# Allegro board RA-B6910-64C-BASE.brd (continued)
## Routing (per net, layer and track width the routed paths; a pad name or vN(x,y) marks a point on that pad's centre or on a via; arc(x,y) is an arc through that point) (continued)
N17880169: length 4.9
  TOP w0.201: R153.2 52.63,90.73 v1(52.25,90.34) v3(52.25,89.08)
  BOTTOM w0.201: v3(52.25,89.08) v1(52.25,90.34)
N17880198: length 15.9
  TOP w0.201: U2.1 61.97,84.38 61.32,85.03 U2.19 56.75,85.03 56.12,85.65 R150.2 55.46,84.89 55.31,84.74 52.47,84.74 v1(52.16,85.05) 51.3,85.91 Q4.3
  BOTTOM w0.201: v3(51.56,85.6) 51.61,85.6 v1(52.16,85.05)
N17880220: length 4
  TOP w0.201: R156.1 65.77,90.22 v1(65.77,90.22) 65.13,89.58 U2.9
  BOTTOM w0.201: v1(65.77,90.22) 65.79,90.21 v3(65.79,89.28)
N17885472: length 3.7
  TOP w0.201: R125.1 126.1,150.8 125.47,150.17 v1(125.47,149.73) U1.91
  BOTTOM w0.201: v3(126.24,149.73) v1(125.47,149.73)
N17885725: length 5.6
  TOP w0.201: v1(116.33,135.25) 116.18,135.1 U1.132 113.75,135.1 112.94,134.29 R116.1
  BOTTOM w0.201: v3(116.33,136.27) v1(116.33,135.25)
N17885726: length 9.6
  TOP w0.201: v1(117.22,135.25) 116.56,134.6 U1.133 114.01,134.6 113.07,133.66 110.48,133.66 110.1,134.04 R121.1
  BOTTOM w0.201: v3(117.73,136.14) 117.73,135.76 v1(117.22,135.25)
N17894131: length 2.5
  TOP w0.201: R145.1 v1(139.79,150.85) 139.82,150.88 Q3.1
  BOTTOM w0.201: v3(139.79,149.99) v1(139.79,150.85)
N17894135: length 8.6
  TOP w0.201: Q3.3 137.53,152.01 136.73,151.21 R143.1 135.63,150.68 134.47,149.52 U1.73 134.47,147.98 v1(135.26,147.19)
  BOTTOM w0.201: v3(136.14,147.19) v1(135.26,147.19)
N17894645: length 4.1
  TOP w0.201: U1.78 131.97,149.31 v1(132.37,149.7) 132.58,149.91 R140.1
  BOTTOM w0.201: v1(132.37,149.7) 132.47,149.6 v3(132.47,148.55)
N17894809: length 3.6
  TOP w0.201: R128.1 128.39,150.55 127.97,150.13 v1(127.97,149.73) U1.86
  BOTTOM w0.201: v3(128.78,149.73) v1(127.97,149.73)
N17894927: length 5.2
  TOP w0.201: v1(124.21,155.07) 124.08,155.19 124.08,156.72 123.92,156.87 R117.1 122.65,156.87 122.29,156.52 Q1.1
  BOTTOM w0.201: v3(124.08,155.96) 124.08,155.19 v1(124.21,155.07)
N17894931: length 8
  TOP w0.201: U1.104 118.97,149.45 v1(119.24,149.72) R113.1 119.52,151.21 119.85,151.54 119.85,154.03 120.05,154.23 Q1.3
  BOTTOM w0.201: v1(119.24,149.72) 119.36,149.61 v3(120.14,149.61)
N17899016: length 3.9
  TOP w0.201: R137.1 138.31,141.28 v1(138.17,141.13) 137.64,140.6 U1.60
  BOTTOM w0.201: v1(138.17,141.13) 137.75,140.72 v3(137.29,140.72)
N17899017: length 5
  TOP w0.201: v1(135.13,140.33) 135.36,140.1 U1.59 138.26,140.1 138.42,140.26 R136.1
  BOTTOM w0.201: v1(135.13,140.33) 135.15,140.36 v3(135.15,141.35)
N17899018: length 5.7
  TOP w0.201: U1.54 137.58,137.6 138.62,136.55 140.96,136.55 R129.1
N17899019: length 3.9
  TOP w0.201: U1.61 137.22,141.1 v1(138.14,142.02) 138.15,142.02 138.43,142.29 R139.1
  BOTTOM w0.201: v1(138.14,142.02) 138.05,142.11 v3(137.29,142.11)
N17899020: length 7.5
  TOP w0.201: R132.1 138.67,138.23 137.8,139.1 U1.57 134.46,139.1 v1(133.22,140.33)
  BOTTOM w0.201: v3(132.33,140.33) v1(133.22,140.33)
N17899021: length 6.3
  TOP w0.201: v1(134.24,140.33) 134.98,139.6 U1.58 138.32,139.6 138.67,139.25 R134.1
  BOTTOM w0.201: v3(133.86,141.35) 133.86,140.72 v1(134.24,140.33)
N17899022: length 8.2
  TOP w0.201: R126.1 138.55,135.94 137.89,136.6 U1.52 133.02,136.6 v1(132.33,137.29)
  BOTTOM w0.201: v3(131.32,137.29) v1(132.33,137.29)
N17905147: length 129.4
  TOP w0.201: v1(141.72,89.59) 141.72,91.24 143.7,93.21 R75.1 ; v2(105.41,121.96) 105.41,120.4 108.07,117.74 108.07,114.16 108.36,113.87 R248.1 109.08,110.92 107.95,109.79 107.95,104.64 YJ1.C7_2
  SIG1 w0.15: v2(105.41,121.96) 102.43,121.96 91.56,111.09 88.8,111.09 83.93,106.22 83.93,92.39 85.71,90.61 92.91,90.61 94.35,89.17 141.31,89.17 v1(141.72,89.59)
N17905148: length 140.2
  TOP w0.201: v1(143.5,89.59) 143.5,91.69 143.88,92.07 R81.1 ; YJ1.C8_2 106.82,100.38 109.4,100.38 112.52,103.5 112.52,108.5 110.1,110.92 R247.1 110.57,113.87 111.22,114.52 111.22,119.65 v2(108.93,121.94)
  SIG1 w0.15: v1(143.5,89.59) 142.7,88.79 94.19,88.79 92.75,90.23 85.55,90.23 83.55,92.23 83.55,106.37 88.64,111.47 91.41,111.47 102.48,122.55 108.32,122.55 v2(108.93,121.94)
N17912152: length 7.3
  TOP w0.201: R321.1 112.64,135.69 113.02,136.07 113.02,136.58 113.54,137.1 U1.128 116.01,137.1 116.08,137.03 116.79,137.03 v1(117.35,137.59)
  BOTTOM w0.201: v3(117.35,138.56) v1(117.35,137.59)
N17912154: length 5.6
  TOP w0.201: R323.1 112.64,136.96 113.28,137.6 U1.127 v1(116.4,137.6)
  BOTTOM w0.201: v3(115.95,138.43) 115.95,138.05 v1(116.4,137.6)
N17933627: length 8.7
  TOP w0.381: R265.2 R266.2 C150.2 388.74,47.55 389.12,47.93 v1(390.4,47.93) 392.17,47.93 392.61,47.49 Q10.1
  BOTTOM w0.381: v1(390.4,47.93) 390.32,48.01 v3(389.64,48.01)
N17933645: length 6.5
  TOP w0.381: Q10.3 391.66,43.74 v1(390.05,42.13) 389.78,41.86 R262.2 R263.1
  BOTTOM w0.381: v3(390.02,43.05) 390.02,42.16 v1(390.05,42.13)
N17933655: length 3
  TOP w0.381: Q9.1 389.88,39.42 v1(389.6,39.7) R263.2
  BOTTOM w0.381: v3(389.64,40.64) 389.64,39.74 v1(389.6,39.7)
N17959753: length 6.5
  TOP w0.201: R250.1 138.67,137.09 137.66,138.1 U1.55 135.04,138.1 v1(134.23,137.29)
  BOTTOM w0.201: v1(134.23,137.29) 134.62,136.9 v3(134.62,136.4)
N17959756: length 10.3
  TOP w0.201: v1(133.34,137.29) 134.65,138.6 U1.56 137.72,138.6 138.62,137.7 140.51,137.7 141.04,138.23 R251.1
  BOTTOM w0.201: v3(133.1,136.4) 133.1,137.04 v1(133.34,137.29)
N17959810: length 7.9
  TOP w0.201: U1.41 137.91,131.1 v1(139.33,129.68) 139.56,129.45 141.89,129.45 R249.1
  BOTTOM w0.201: v3(138.3,129.67) 139.32,129.67 v1(139.33,129.68)
N17988063: length 2.6
  TOP w0.201: U10.2 102.76,131.4 102.86,131.5 R291.2
N17988151: length 7.5
  TOP w0.201: R301.2 99.56,135.82 99.19,135.45 99.19,134.4 99.6,134 U10.6
N17988854: length 3.7
  TOP w0.201: R290.2 102.99,130.48 102.72,130.75 v1(102.49,130.75) U10.1
  BOTTOM w0.201: v1(102.49,130.75) 101.85,130.11 v3(101.85,129.92)
N17988900: length 2.6
  TOP w0.201: R303.2 101.84,134.8 101.69,134.65 U10.7
N17997808: length 3.7
  TOP w0.201: R267.1 122.67,149.99 v1(122.97,149.69) U1.96
  BOTTOM w0.201: v3(123.19,148.84) 123.19,149.47 v1(122.97,149.69)
N17998511: length 7.3
  TOP w0.201: v1(133.73,133.48) 133.73,133.86 134.47,134.6 U1.48 137.73,134.6 138.67,133.66 R269.1
  BOTTOM w0.201: v3(132.72,133.48) v1(133.73,133.48)
N17998908: length 5.4
  TOP w0.201: R272.1 138.42,146.1 137.41,145.1 U1.69 v1(134.94,145.1)
  BOTTOM w0.201: v1(134.94,145.1) 134.87,145.16 v3(133.99,145.16)
N18001007: length 6.2
  TOP w0.201: U10.12 94.25,133.35 93.13,134.47 R299.1 92.55,134.27 92.14,133.86 90.72,133.86 90.26,134.32 R298.1
N18001035: length 6.7
  TOP w0.201: U10.11 94.34,134 93.09,135.24 93.09,135.68 92.95,135.82 R296.1 92.55,135.54 92.22,135.21 90.54,135.21 90.26,135.48 R295.1
N18001064: length 8.4
  TOP w0.201: U10.10 94.43,134.65 93.61,135.46 93.61,136.43 v1(93.3,136.74) 92.95,137.09 R294.1 92.55,136.63 92.35,136.43 90.46,136.43 90.26,136.63 R293.1
  BOTTOM w0.201: v1(93.3,136.74) 93.22,136.82 v3(93.22,137.67)
N18001098: length 9.5
  TOP w0.201: R289.1 90.26,137.96 90.46,137.76 92.27,137.76 92.55,138.04 R292.1 93.42,138.48 94.12,137.78 v1(94.12,137.29) 94.12,135.69 94.51,135.3 U10.9
  BOTTOM w0.201: v3(95.12,137.29) v1(94.12,137.29)
N18008506: length 23.1
  TOP w0.201: J4.14 221.08,167.31 226,167.31 228.63,169.94 v1(237.65,169.94) 237.84,169.75 R281.1 R101.1 R312.1
  BOTTOM w0.201: v3(237.49,169.04) 237.49,169.78 v1(237.65,169.94)
N18009865: length 215.6
  TOP w0.201: v1(141.59,125.02) 138.67,122.1 138.67,121.21 138.06,120.6 R279.2 137.66,119.94 136.96,119.25 Q11.1 ; v2(305.93,166.3) 306.82,165.41 326.25,165.41 326.51,165.66 R98.2
  SIG1 w0.15: v2(305.93,166.3) 304.67,165.04 304.67,163.26 291.87,150.45 165.38,150.45 143.76,128.83 v1(141.59,128.83)
  SIG2 w0.16: v1(141.59,128.83) v1(141.59,125.02)
N18010804: length 6.2
  TOP w0.201: R104.2 R285.2 103.39,156.29 103.93,156.83 Q13.1 v1(105.02,155.92)
  BOTTOM w0.201: v3(106.05,155.96) 105.06,155.96 v1(105.02,155.92)
N18021498: length 5.9
  TOP w0.201: R58.1 112.66,129.97 114.29,131.6 U1.139 v1(116.33,131.6)
  BOTTOM w0.201: v1(116.33,131.6) 116.46,131.47 v3(116.46,130.68)
N18217749: length 11.8
  TOP w0.201: R314.1 141.98,127.94 140.3,126.27 138.43,126.27 137.39,127.31 v1(137.39,127.84) 136.7,128.52 135.63,128.52 135.29,128.86 135.29,129.27 135.62,129.6 U1.38
  BOTTOM w0.201: v1(137.39,127.84) 137.41,127.81 v3(137.41,126.87)
N18217752: length 13.7
  TOP w0.201: U1.39 135.32,130.1 134.79,129.56 134.79,128.65 135.47,127.97 136.24,127.97 v1(136.4,127.81) 136.4,127.04 137.68,125.76 140.51,125.76 141.68,126.93 R315.1
  BOTTOM w0.201: v3(135.26,127.76) 136.35,127.76 v1(136.4,127.81)
N18217823: length 12.7
  TOP w0.201: v1(133.19,132.11) 133.7,131.6 U1.42 137.92,131.6 138.85,130.67 139.05,130.67 139.77,129.96 144.02,129.96 R316.1
  BOTTOM w0.201: v1(133.19,132.11) 133.04,131.95 v3(132.33,131.95)
N18217826: length 11.3
  TOP w0.201: v1(135.02,132.11) 135.03,132.1 v3(136.42,132.1) 137.92,132.1 138.85,131.18 139.76,131.18 140.48,130.46 143.51,130.46 R317.1
  BOTTOM w0.201: v3(136.42,132.1) 135.03,132.1 v1(135.02,132.11)
N18217886: length 9.2
  TOP w0.201: R322.1 143.72,133.02 143.26,132.56 143.26,132.01 142.72,131.47 140.9,131.47 140.18,132.19 138.94,132.19 138.03,133.1 U1.45
N18217888: length 12.4
  TOP w0.201: v1(134.11,132.11) 134.74,132.74 135.23,132.74 135.37,132.6 U1.44 137.95,132.6 138.87,131.68 139.97,131.68 140.69,130.97 143,130.97 R320.1
  BOTTOM w0.201: v3(134.24,131.06) 134.24,131.99 v1(134.11,132.11)
N18217940: length 7.6
  TOP w0.201: v1(141.73,135.64) 141.37,135.27 R324.1 141.37,134.55 141.11,134.29 138.73,134.29 137.92,135.1 U1.49
  BOTTOM w0.201: v3(142.75,135.64) v1(141.73,135.64)
N18225889: length 3.4
  TOP w0.508: R331.2 R332.2 330.64,169.73 Q14.1
N18236302: length 3.4
  TOP w0.508: Q15.1 235.77,172.52 R350.2 R349.2
N18236637: length 3.4
  TOP w0.508: Q16.1 136.39,163.59 135.75,164.22 R355.2 R354.2
N18282960: length 2.3
  TOP w0.381: R356.1 131.71,61.24 131.56,61.39 J11.1

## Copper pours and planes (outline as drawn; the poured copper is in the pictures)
GND on TOP: 378.89,120.37 381.43,120.37 381.69,120.11 381.69,111.22 381.43,110.97 372.41,110.97 372.1,111.29 372.1,118.08 372.35,118.34 376.86,118.34
GND on TOP: 405.5,48.57 405.5,44.76 405.75,44.5 408.93,44.5 409.44,45.01 409.44,46.92 409.82,47.3 412.36,47.3 412.99,46.66 414.77,46.66 415.15,47.04 415.15,48.19 414.52,48.82 405.75,48.82
GND on TOP: 8.75,42.34 9.13,42.73 10.78,42.73 11.67,43.61 16.5,43.61 18.4,41.71 23.99,41.71 24.37,41.33 24.37,31.42 23.99,31.04 9.01,31.04 8.75,31.3
GND on TOP: 387.21,51.49 392.93,51.49 393.05,51.62 396.99,51.62 397.37,51.23 397.37,49.71 396.74,49.08 387.59,49.08 387.09,49.58 387.09,51.36
GND on TOP: 25.71,121.38 25.71,113.01 25.63,112.93 23.37,112.93 22.78,113.52 22.78,121.26 23.29,121.77 25.32,121.77
GND on TOP: 384.67,13.01 382.77,13.01 382.39,13.39 382.39,15.8 380.86,17.33 380.86,25.33 381.37,25.83 384.67,25.83 384.93,25.58 384.93,13.26
GND on TOP: 400.42,27.36 398.01,27.36 397.63,27.74 397.63,29.52 398.52,30.41 400.55,30.41 400.8,30.15 400.8,27.74
GND on TOP: outline of 168 points within 1.02,1.02 428.98,186.98 ; 7 cut-outs
GND on TOP: 395.72,21.26 393.31,21.26 392.93,21.64 392.93,23.42 393.44,23.93 395.72,23.93 396.1,23.55 396.1,21.64
GND on TOP: 47.23,42.34 47.61,42.73 49.27,42.73 50.15,43.61 54.98,43.61 56.89,41.71 62.47,41.71 62.85,41.33 62.85,31.42 62.47,31.04 47.49,31.04 47.23,31.3
GND on TOP: 408.1,105.13 409.24,103.99 417.1,103.99 417.12,104 418.39,104 418.84,104.45 418.84,124.01 418.58,124.26 408.68,124.26 408.1,123.68
GND on TOP: 84.19,113.59 84.95,112.83 88,112.83 89.4,114.23 89.4,125.28 89.02,125.66 89.02,129.21 87.87,130.36 84.44,130.36 84.19,130.1
GND on BOTTOM: outline of 87 points within 1.02,1.02 428.98,186.98 ; 5 cut-outs
GND on GND1: 2,1.02 1.3,1.3 1.02,2 1.02,136.65 2.84,136.65 2.84,130.81 3.2,129.83 4.11,129.32 4.75,129.35 5.32,129.64 5.41,129.72 5.49,129.8 68.12,129.8 68.19,129.72 68.28,129.64 68.85,129.35 69.49,129.32 70.4,129.83 70.76,130.81 70.76,145.28 80,145.28 82.13,146.17 83.02,148.3 83.02,186 83.3,186.7 84,186.98 346,186.98 346.7,186.7 346.98,186 346.98,148.3 347.87,146.17 350,145.28 359.14,145.28 359.14,129.46 359.12,129.44 359.12,125.35 359.82,124.64 378.37,124.64 381.92,121.1 382.04,121.1 382.04,121.62 379.65,124.01 379.65,125.42 379.63,125.44 380.35,126.16 380.35,129.8 424.42,129.8 424.49,129.72 424.58,129.64 425.15,129.35 425.79,129.32 426.7,129.83 427.06,130.81 427.06,136.48 427.23,136.65 428.75,136.65 428.98,136.42 428.98,2 428.7,1.3 428,1.02 ; 5 cut-outs
GND on SIG1: 342.32,119.88 331.84,130.36 159.5,130.36 157.98,131.88 157.98,134.17 170.04,146.23 293.49,146.23 312.16,164.9 323.71,164.9 329.17,170.36 329.17,171.63 328.16,172.65 302.25,172.65 300.79,171.19 300.79,160.26 291.2,150.68 206.75,150.68 206.24,151.18 206.24,153.22 219.57,166.55 224.78,166.55 226.68,168.46 226.68,171.76 225.92,172.52 206.75,172.52 205.48,171.25 205.48,160.84 199.63,154.99 165.22,154.99 164.45,155.76 164.45,168.46 163.18,169.73 158.99,169.73 156.83,167.57 156.83,156.14 154.42,153.72 149.34,153.72 145.4,157.66 145.4,171.76 143.75,173.41 91.94,173.41 88.38,169.85 88.38,134.93 86.22,132.77 72.63,132.77 71.11,134.29 71.11,145.28 80,145.28 82.13,146.17 83.02,148.3 83.02,186 83.3,186.7 84,186.98 346,186.98 346.7,186.7 346.98,186 346.98,148.3 347.87,146.17 350,145.28 359.02,145.28 359.02,124.51 354.38,119.88
GND on SIG1: 138.93,82.22 144.26,76.89 157.6,76.89 159.37,78.67 159.37,83.49 159.88,84 166.23,84 166.87,83.37 166.87,65.46 164.58,63.17 164.58,62.79 164.84,62.54 165.09,62.54 165.85,63.3 167.88,63.3 168.14,63.05 168.14,59.43 167.26,58.55 163.7,58.55 159.69,54.54 101.34,54.54 80.89,74.98 75.68,74.98 70.73,79.94 70.73,85.91 76.32,91.49 81.14,91.49 90.41,82.22
GND on SIG1: 154.68,125.78 163.57,125.78 166.11,123.24 166.11,110.04 157.47,101.4 122.29,101.4 113.4,110.29 94.73,110.29 93.72,111.31 93.72,113.34 101.72,121.34 104.89,121.34 105.4,120.83 105.4,118.54 103.37,116.51 103.37,113.46 104,112.83 128.13,112.83 133.09,117.78 146.67,117.78
GND on SIG1: 195.32,96.95 178.93,96.95 175,93.02 175,73.08 177.03,71.05 177.03,68.25 179.82,65.46 183.63,65.46 217.79,99.62 343.91,99.62 356.86,112.58 356.86,115.62 356.35,116.13 341.11,116.13 329.3,127.94 199.63,127.94 197.09,125.4 197.09,98.73
GND on SIG1: 2,1.02 1.42,1.21 1.06,1.7 1.03,1.85 1.02,2 1.02,136.65 1.04,136.67 1.42,136.67 1.51,136.58 1.51,20.25 20.06,1.7 341.37,1.7 376.8,37.14 417.44,37.14 420.11,39.8 420.11,65.33 406.9,78.54 406.9,129.8 424.42,129.8 424.49,129.72 424.58,129.64 425.15,129.35 425.79,129.32 426.7,129.83 427.06,130.81 427.06,136.48 427.23,136.65 428.75,136.65 428.98,136.42 428.98,2 428.7,1.3 428,1.02
GND on GND2: 2,1.02 1.3,1.3 1.02,2 1.02,136.65 2.84,136.65 2.84,130.81 3.2,129.83 4.11,129.32 4.75,129.35 5.32,129.64 5.41,129.72 5.49,129.8 16.12,129.8 16.12,129.47 17.26,128.32 20.18,128.32 20.44,128.07 20.44,125.53 21.58,124.39 43.93,124.39 44.82,125.28 44.82,129.8 68.12,129.8 68.19,129.72 68.28,129.64 68.85,129.35 69.49,129.32 70.4,129.83 70.76,130.81 70.76,145.28 80,145.28 82.13,146.17 83.02,148.3 83.02,186 83.3,186.7 84,186.98 346,186.98 346.7,186.7 346.98,186 346.98,148.3 347.87,146.17 350,145.28 359.14,145.28 359.14,130.81 359.5,129.83 360.41,129.32 361.05,129.35 361.62,129.64 361.71,129.72 361.79,129.8 371.77,129.8 372.86,128.7 372.86,125.28 372.73,125.15 372.73,125.02 372.86,124.89 380.74,124.89 381.5,125.66 400.17,125.66 400.8,126.29 400.8,129.8 424.42,129.8 424.49,129.72 424.58,129.64 425.15,129.35 425.79,129.32 426.7,129.83 427.06,130.81 427.06,136.48 427.23,136.65 428.75,136.65 428.98,136.42 428.98,2 428.7,1.3 428,1.02 ; 1 cut-out
GND on SIG2: 179.69,81.59 359.4,81.59 386.2,54.79 386.2,36.76 383.53,34.09 381.5,34.09 345.68,69.9 185.41,69.9 179.44,75.87 179.44,81.33
GND on SIG2: 2,1.02 1.3,1.3 1.02,2 1.02,60.9 2.28,62.16 70.22,62.16 96.76,35.61 188.97,35.61 193.54,40.19 193.54,53.65 194.68,54.79 337.68,54.79 382.51,9.96 382.51,3.36 383.15,2.72 405.37,2.72 405.5,2.59 409.18,2.59 410.2,3.61 410.2,40.69 410.96,41.46 425.95,41.46 427.47,42.98 427.47,70.16 423.28,74.35 413.25,74.35 401.82,85.78 401.82,129.8 424.42,129.8 424.49,129.72 424.58,129.64 425.15,129.35 425.79,129.32 426.7,129.83 427.06,130.81 427.06,136.48 427.23,136.65 428.75,136.65 428.98,136.42 428.98,2 428.7,1.3 428,1.02
GND on SIG2: 122.74,80.63 144.13,59.24 144.13,56.31 142.74,54.92 100.7,54.92 89.65,65.97 89.65,78.22 92.06,80.63
GND on SIG2: 197.22,117.02 196.84,117.4 196.84,128.96 169.66,156.14 151.25,156.14 148.96,158.42 148.96,161.47 151.37,163.88 180.46,163.88 183.76,160.58 230.75,160.58 234.18,164.01 303.39,164.01 305.3,162.11 317.11,162.11 319.52,164.52 319.52,165.28 320.28,166.04 320.66,166.04 326.38,171.76 330.19,171.76 330.7,172.27 330.44,172.52 302.12,172.52 296.79,167.19 243.83,167.19 237.92,173.09 206.94,173.09 201.16,167.31 186.81,167.31 183.38,170.74 165.22,170.74 161.28,174.68 151.88,174.68 151.25,174.04 113.27,174.04 104.13,164.9 93.46,164.9 88.64,160.07 88.64,138.1 81.27,130.74 70.75,130.74 70.76,130.81 70.76,145.28 80,145.28 82.13,146.17 83.02,148.3 83.02,186 83.3,186.7 84,186.98 346,186.98 346.7,186.7 346.98,186 346.98,148.3 347.87,146.17 350,145.28 358.18,145.28 358.71,144.75 358.71,144.71 358.73,144.7 358.95,144.7 359.01,144.63 359.01,125.78 358.26,125.02 344.16,125.02 336.16,117.02
VDD5V on TOP: 386.45,60.63 387.09,61.27 391.02,61.27 391.4,60.89 391.4,55.81 392.29,54.92 392.29,53.27 392.04,53.01 387.47,53.01 386.96,53.52 386.96,55.55 386.45,56.06
VDD5V on TOP: 400.42,21.9 398.01,21.9 397.37,22.53 397.37,26.09 397.75,26.47 400.17,26.47 400.67,25.96 400.67,22.15
VDD5V on SIG2: 387.85,55.81 406.39,55.81 409.56,52.63 409.56,25.2 406.14,21.77 395.09,21.77 387.09,29.77 387.09,55.04
VDD12V on TOP: 26.41,122.74 26.41,113.08 26.53,112.96 79.87,112.96 81.65,114.73 81.65,128.7 81.4,128.96 74.67,128.96 70.35,124.64 46.09,124.64 45.71,125.02 45.71,128.06 45.42,128.36 45.42,128.45 45.11,128.76 23.73,128.76 23.24,128.27 23.24,123.57 23.57,123.24 25.9,123.24
VDD12V on TOP: 274.56,91.49 271.77,94.29 271.77,126.55 264.4,133.91 155.31,133.91 149.47,139.75 149.47,145.6 143.12,151.95 143.12,154.49 141.47,156.14 130.8,156.14 126.74,160.2 108.32,160.2 104.89,163.63 104.89,172.77 105.15,173.03 105.16,173.03 107.39,175.26 113.79,175.26 115.43,173.62 115.43,170.23 115.18,169.98 110.86,169.98 110.35,169.47 110.35,167.19 110.73,166.8 130.29,166.8 134.23,170.74 139.82,170.74 147.25,163.31 147.25,157.6 151.88,152.96 199.63,152.96 200.4,153.72 200.4,173.98 200.79,174.37 210.06,174.37 210.57,173.86 210.57,172.78 210.56,172.77 210.56,170.49 210.17,170.11 206.49,170.11 205.98,169.6 205.98,157.15 210.17,152.96 294.38,152.96 295.39,153.98 295.39,172.96 296.55,174.12 305.31,174.12 306.06,173.37 306.06,170.23 305.81,169.98 301.36,169.98 300.98,169.6 300.98,161.72 301.49,161.22 327.27,161.22 328.67,159.82 328.67,95.3 324.86,91.49 ; 1 cut-out
VDD12V on TOP: 401.69,128.38 401.69,124.77 405.25,121.21 405.25,107.62 404.61,106.99 386.2,106.99 382.39,110.8 382.39,121.21 379.47,124.13 379.47,128.14 379.86,128.53 379.86,128.66 379.95,128.76 401.32,128.76
VDD12V on TOP: 393.69,54.16 398.13,54.16 398.26,54.03 398.26,53.39 398.39,53.27 399.4,53.27 399.66,53.01 399.66,52.76 399.4,52.5 397.63,52.5 397.5,52.38 393.44,52.38 393.31,52.5 393.31,53.77
VDD12V on TOP: 7.48,70.79 31.23,70.79 31.99,70.03 31.99,46.41 29.45,43.87 19.17,43.87 18.53,44.5 11.93,44.5 11.67,44.76 8.88,44.76 6.34,47.3 6.34,69.65
VDD12V on TOP: 402.07,43.61 403.98,43.61 404.87,44.5 404.87,48.57 404.74,48.69 402.71,48.69 402.45,48.44 402.45,45.14 402.07,44.76
VDD12V on TOP: 44.69,72.95 75.81,72.95 76.7,72.06 76.7,45.14 75.3,43.74 57.77,43.74 57.14,44.38 50.15,44.38 49.65,44.88 47.61,44.88 43.8,48.69 43.8,72.06
VDD12V on GND1: 2.66,74.22 80.51,74.22 104.26,50.47 171.82,50.47 220.21,98.86 344.03,98.86 358.52,113.35 367.86,113.35 371.68,109.52 381.52,109.52 382.36,110.37 382.36,121.84 380.1,124.1 380.1,128.7 380.48,129.09 380.99,129.09 380.99,129.59 381.19,129.8 401.82,129.8 401.82,123.5 404.87,120.45 404.87,79.43 350.07,24.63 340.01,24.63 319.39,4.02 20.16,4.02 2.4,21.77 2.4,73.97 ; 3 cut-outs
VDD12V on SIG1: 2.28,21.9 2.28,103.94 13.71,115.37 13.71,123.24 14.91,124.45 21.77,124.45 23.04,125.72 23.04,128.09 23.9,128.09 24.57,128.76 45,128.76 45.77,127.98 45.77,124.94 46.28,124.43 70.03,124.43 70.54,123.92 70.54,120.75 62.73,112.94 62.73,82.35 70.86,74.22 80.51,74.22 101.37,53.36 157.98,53.36 160.49,50.85 172.2,50.85 220.21,98.86 344.03,98.86 360.92,115.75 360.92,124.2 361.32,124.59 378.97,124.59 379.48,125.09 379.48,128.38 379.86,128.76 401.15,128.76 401.82,128.09 401.82,123.5 404.87,120.45 404.87,77.9 418.71,64.06 418.71,40.19 416.93,38.41 375.02,38.41 340.63,4.02 20.16,4.02 ; 3 cut-outs
VDD12V on SIG2: 6.47,65.71 2.4,69.78 2.4,104.07 10.28,111.94 10.28,114.61 9.51,115.37 9.51,118.67 8.88,119.31 3.93,119.31 2.66,120.58 2.66,123.5 3.42,124.26 22.6,124.26 22.98,124.64 22.98,128.14 23.04,128.14 23.66,128.76 45.37,128.76 45.46,128.67 45.46,125.02 45.96,124.51 68.95,124.51 70.6,122.86 70.6,121.59 65.39,116.39 65.39,103.37 64.39,102.36 64.39,98.81 65.39,97.8 65.39,66.47 64.63,65.71
CPLD3.3V on TOP: 118.86,116.39 117.46,117.78 117.46,119.43 118.23,120.2 123.69,120.2 124.7,121.21 128.51,121.21 128.77,120.96 128.77,117.27 127.88,116.39
CPLD3.3V on TOP: 186.81,102.54 194.43,102.54 194.81,102.16 194.81,51.62 192.78,49.58 187.7,49.58 185.41,51.87 185.41,101.15
CPLD3.3V on TOP: 410.96,44.25 410.96,38.92 411.34,38.53 414.14,38.53 414.52,38.92 414.52,44.12 414.14,44.5 411.22,44.5
CPLD3.3V on SIG1: 180.08,98.73 180.08,123.75 183.38,127.05 194.93,127.05 196.33,125.66 196.33,98.61 195.06,97.34 181.47,97.34
CPLD3.3V on SIG1: 92.57,153.98 92.06,154.49 92.06,164.65 93.21,165.79 114.54,165.79 125.47,154.87 125.47,154.61 125.59,154.49 137.02,154.49 143.25,148.26 143.25,146.61 143.12,146.48 118.86,146.48 112.38,152.96 105.53,152.96 104.51,153.98
CPLD3.3V on SIG1: 163.18,168.46 163.18,155.25 161.53,153.6 159.25,153.6 157.98,154.87 157.98,167.82 159.37,169.22 162.42,169.22
CPLD3.3V on SIG2: 66.79,72.06 66.79,81.71 67.17,82.1 72.38,82.1 100.19,54.28 145.91,54.28 152.77,47.42 164.33,47.42 171.19,54.28 192.65,54.28 193.16,53.77 193.16,40.88 188.46,36.18 102.67,36.18
CPLD3.3V on SIG2: 165.98,117.02 163.31,119.69 122.29,119.69 119.5,122.48 119.5,125.66 120.39,126.55 120.39,126.67 120.13,126.93 113.15,126.93 113.4,126.67 113.4,126.42 108.83,126.42 104.89,130.36 104.89,132.77 105.27,133.15 105.91,133.15 107.43,134.67 107.43,145.98 111.75,150.29 113.65,150.29 115.05,151.69 129.28,151.69 131.05,153.47 141.09,153.47 142.86,155.25 169.92,155.25 196.33,128.83 196.33,121.47 191.89,117.02 ; 3 cut-outs
CPLD3.3V on SIG2: 410.07,53.39 410.07,44.25 411.98,42.34 425.44,42.34 426.46,43.36 426.46,68 421.38,73.08 413.76,73.08 383.28,103.56 180.71,103.56 180.08,102.92 180.08,86.03 184.01,82.1 359.65,82.1 384.86,56.89 406.58,56.89
CPLD3.3V on SIG2: 161.98,171.69 161.98,167.63 161.28,166.93 153.53,166.93 152.77,167.69 152.77,173.54 153.41,174.17 159.5,174.17
CPLD3.3V on SIG2: 89.27,129.72 87.37,131.63 87.37,134.8 89.91,137.34 89.91,138.1 90.54,138.74 97.78,138.74 99.18,140.13 99.18,144.83 92.19,151.82 92.19,158.68 92.32,158.8 96.76,158.8 96.89,158.68 96.89,155.37 97.02,155.25 97.27,155.25 97.27,156.26 97.65,156.64 102.42,156.64 103.3,155.76 103.3,153.22 101.97,151.88 101.97,146.23 103.24,144.96 103.24,139.5 101.31,137.57 100.97,137.92 97.21,134.17 93.72,134.17 92.83,133.28 91.68,133.28 90.54,132.13 91.18,131.5 91.43,131.5 91.43,130.23 90.92,129.72
Net_30 on BOTTOM: 382.03,6.4 382.03,2.97 381.9,2.85 377.84,2.85 377.71,2.97 377.71,6.4 377.84,6.53 381.9,6.53
Net_30 on BOTTOM: 356.86,129.47 360.92,129.47 361.05,129.34 361.05,125.02 360.92,124.89 356.86,124.89 356.73,125.02 356.73,129.34
Net_30 on BOTTOM: 1.89,129.47 4.62,129.47 4.75,129.34 4.75,125.02 4.62,124.89 2.02,124.89 1.77,125.15 1.77,129.34
Net_31 on BOTTOM: 106.32,171.88 110.38,171.88 110.51,171.76 110.51,167.57 110.38,167.44 106.32,167.44 106.19,167.57 106.19,171.76
Net_31 on BOTTOM: 296.92,171.88 300.98,171.88 301.11,171.76 301.11,167.57 300.98,167.44 296.92,167.44 296.79,167.57 296.79,171.76
Net_31 on BOTTOM: 201.62,171.88 205.68,171.88 205.81,171.76 205.81,167.57 205.68,167.44 201.62,167.44 201.49,167.57 201.49,171.76
Net_71 on TOP (solid shape): outline of 184 points within 88.26,166.68 91.81,170.23
Net_72 on TOP (solid shape): outline of 184 points within 335.52,170.49 339.08,174.04
Net_73 on TOP (solid shape): outline of 184 points within 12.82,12.75 16.37,16.31
Net_74 on TOP (solid shape): outline of 184 points within 420.87,16.69 424.42,20.25
USB5V on TOP: 386.3,2.74 386.83,2.21 388.36,2.21 388.61,2.47 388.61,6.93 392.04,10.36 392.04,23.93 390.51,25.45 390.51,28.5 389.88,29.14 388.1,29.14 387.97,29.01 387.97,25.96 387.85,25.83 386.58,25.83 386.3,25.56
N17785334 on TOP: 394.83,61.14 395.09,61.39 398.26,61.39 398.64,61.01 398.64,57.33 398.01,56.7 398.01,55.04 397.88,54.92 395.34,54.92 394.83,55.43
N17786050 on TOP: 407.28,42.73 407.53,42.47 407.53,39.17 407.15,38.79 404.36,38.79 403.98,39.17 403.98,40.31 403.6,40.69 402.83,40.69 402.07,41.46 402.07,42.6 402.2,42.73
N17801498 on TOP: 396.48,24.69 393.05,24.69 391.28,26.47 391.28,28.88 391.53,29.14 396.36,29.14 396.86,28.63 396.86,25.07

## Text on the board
Ref Des/Silkscreen Bottom: RE.100B1805171,1804
Ref Des/Silkscreen Top: GND | VDD12V | VDD5V | CPLD3.3V | CPLD DOWN LOAD | Debug pin | V1.00 | 13FEBZ-24HF03151414050320 | SCREW
COMPVAL_TYPE_TOP: GND1
DIMENSION: BACKDRILL_B:NULL:B-S1@TOP-SIG1@
User.14: FIGURE | SIZE | 8.0 | 9.0 | 14.57 | 16.0 | 20.0 | 31.89 | 35.43 | 37.0 | 40.0 | 43.31 | 71.0 | 86.61 | 118.0 | 137.8 | 50.0 | 122.05x47.24 | DRILL CHART: TOP to BOTTOM | ALL UNITS ARE IN MILS | PLATED | NON-PLATED | QTY | 2121 | 123 | 72 | 356 | 208 | 25 | 1 | 48 | 10 | 2 | 100 | 20 | 5 | 4 | 3 | 26
